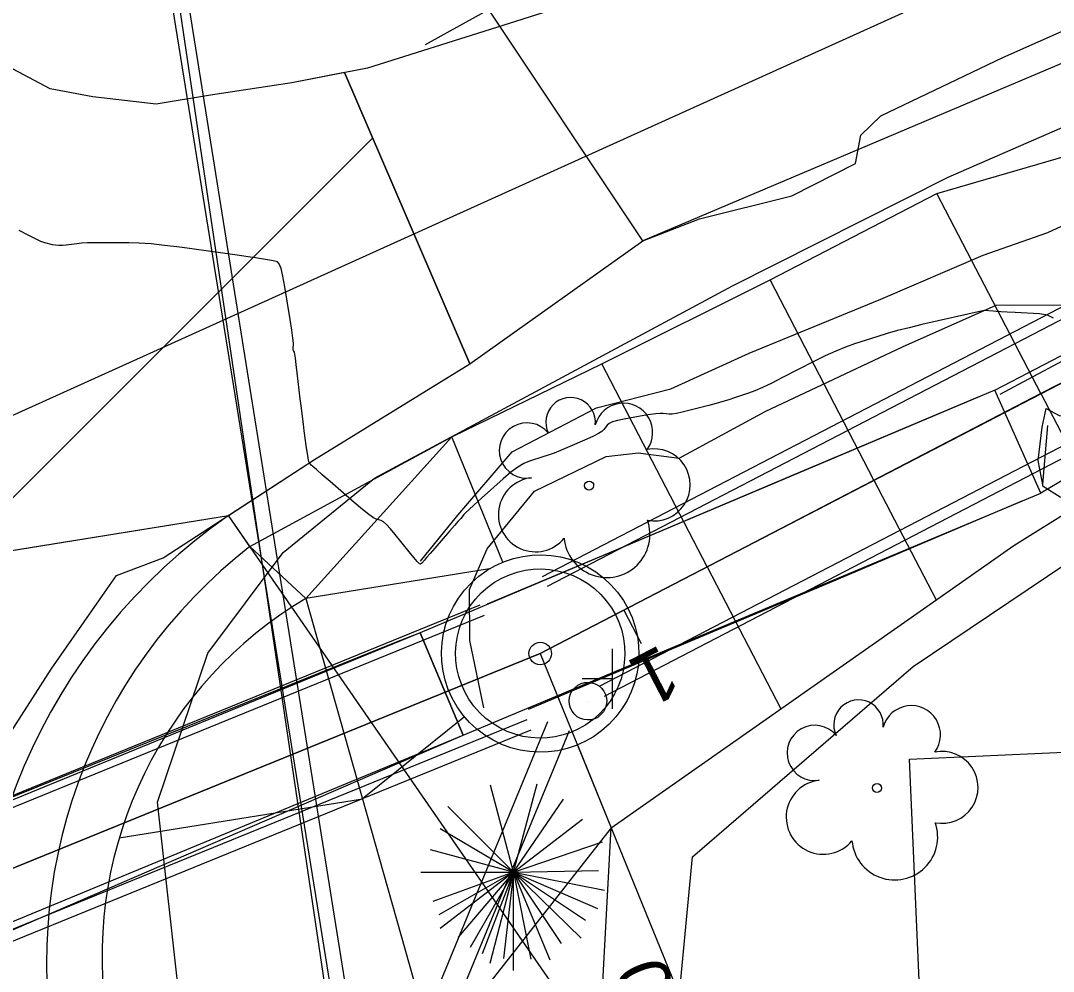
# Model space of a CAD drawing. Extents: x 2030588 to 2035216, y 462285 to 465007.
# Drawn here: x 2031264.6 to 2031319.5, y 464317.2 to 464367.7 of the extents above; entities that cross this region are included whole.
import ezdxf

# ---------------------------------------------------------------- set-up
doc = ezdxf.new("R2010")
doc.units = 0
for name, color, linetype in [('BD_X_Building', 7, 'Continuous'), ('Default', 7, 'Continuous'), ('DR_P_Cells', 7, 'Continuous'), ('DR_P_Culvert', 7, 'Continuous'), ('DR_P_Drive_Pipe', 7, 'Continuous'), ('DR_X_Culvert', 7, 'Continuous'), ('DR_X_Headwall', 7, 'Continuous'), ('DR_X_Storm_Sewer', 7, 'Continuous'), ('DT_P_Pavement_Surface', 7, 'Continuous'), ('DT_P_Slope_Break_Line', 7, 'Continuous'), ('DT_X_Contour_Major', 7, 'Continuous'), ('GE_P_Alignment', 7, 'Continuous'), ('GE_P_Alignment_100_Cardinal_Points', 7, 'Continuous'), ('GE_P_Alignment_100_Stations', 7, 'Continuous'), ('GK_Drainage_Nodes', 7, 'Continuous'), ('MD_P_CONST_LIMITS', 7, 'Continuous'), ('PV_P_EOP', 7, 'Continuous'), ('PV_P_Shoulder', 7, 'Continuous'), ('PV_X_Driveway', 7, 'Continuous'), ('PV_X_EOP', 7, 'Continuous'), ('RW_X_CL', 7, 'Continuous'), ('RW_X_Esmt_SH', 7, 'Continuous'), ('SC_Scratch1', 7, 'Continuous'), ('SN_X_Public', 7, 'Continuous'), ('SV_X_Break_Lines', 7, 'Continuous'), ('UT_X_Cable_TV', 7, 'Continuous'), ('UT_X_Electric', 7, 'Continuous'), ('UT_X_Telecom', 7, 'Continuous'), ('VG_X_Cells', 7, 'Continuous')]:
    doc.layers.add(name, color=color, linetype=linetype)

msp = doc.modelspace()

# ---------------------------------------------------------------- linework, layer by layer
at = {"layer": 'BD_X_Building'}
msp.add_lwpolyline([(2031312.882, 464304.375), (2031312.354, 464316.266), (2031311.814, 464328.452), (2031319.655, 464328.798), (2031324.902, 464329.03), (2031333.154, 464329.394), (2031342.968, 464329.827), (2031348.498, 464330.072), (2031349.056, 464317.507), (2031343.615, 464317.267), (2031344.126, 464305.755), (2031336.745, 464305.429), (2031327.934, 464305.04), (2031320.082, 464304.693)], close=True, dxfattribs=at)
at = {"layer": 'Default'}
for p, q in [((2031316.362, 464348.067), (2031316.362, 464348.067)), ((2031315.519, 464347.736), (2031315.519, 464347.736)), ((2031316.5, 464347.757), (2031316.5, 464347.757)), ((2031316.641, 464347.854), (2031316.641, 464347.854)), ((2031305.563, 464343.535), (2031305.563, 464343.535)), ((2031318.806, 464342.593), (2031318.806, 464342.593)), ((2031317.813, 464342.184), (2031317.813, 464342.184)), ((2031295.89, 464339.435), (2031295.89, 464339.435)), ((2031307.926, 464337.972), (2031307.926, 464337.972)), ((2031289.387, 464336.696), (2031289.387, 464336.696)), ((2031285.803, 464335.154), (2031285.803, 464335.154)), ((2031284.43, 464334.622), (2031284.43, 464334.622)), ((2031298.264, 464333.912), (2031298.264, 464333.912)), ((2031291.567, 464331.1), (2031291.567, 464331.1)), ((2031288.089, 464329.716), (2031288.089, 464329.716)), ((2031286.679, 464329.115), (2031286.679, 464329.115))]:
    msp.add_line(p, q, dxfattribs=at)
at = {"layer": 'DR_P_Cells'}
for centre, major_axis in [((2031292.185, 464334.061), (3.66, -3.763)), ((2031292.185, 464334.061), (3.137, -3.225)), ((2031294.719, 464331.527), (0.697, -0.717))]:
    msp.add_ellipse(centre, major_axis=major_axis, ratio=0.999989, dxfattribs=at)
at = {"layer": 'DR_P_Culvert'}
for p, q in [((2031292.309, 464338.162), (2031339.345, 464362.578)), ((2031292.578, 464337.645), (2031339.613, 464362.06)), ((2031295.342, 464332.32), (2031342.377, 464356.735)), ((2031295.611, 464331.802), (2031342.646, 464356.218)), ((2031288.982, 464336.625), (2031221.38, 464309.094)), ((2031289.202, 464336.085), (2031221.6, 464308.554)), ((2031291.465, 464330.528), (2031223.863, 464302.998)), ((2031291.685, 464329.988), (2031224.083, 464302.457))]:
    msp.add_line(p, q, dxfattribs=at)
at = {"layer": 'DR_P_Drive_Pipe'}
for p, q in [((2031285.496, 464313.266), (2031292.582, 464330.451)), ((2031287.024, 464313.693), (2031293.738, 464329.975))]:
    msp.add_line(p, q, dxfattribs=at)
at = {"layer": 'DR_X_Culvert'}
for p, q in [((2031316.362, 464348.067), (2031341.014, 464360.907)), ((2031343.516, 464357.134), (2031318.806, 464342.593)), ((2031316.362, 464348.067), (2031285.803, 464335.154)), ((2031318.806, 464342.593), (2031316.362, 464348.067)), ((2031318.806, 464342.593), (2031316.362, 464348.067)), ((2031288.089, 464329.716), (2031318.806, 464342.593)), ((2031285.803, 464335.154), (2031218.984, 464307.814)), ((2031288.089, 464329.716), (2031285.803, 464335.154)), ((2031285.803, 464335.154), (2031288.089, 464329.716)), ((2031221.368, 464302.132), (2031288.089, 464329.716))]:
    msp.add_line(p, q, dxfattribs=at)
at = {"layer": 'DR_X_Headwall'}
msp.add_line((2031318.914, 464343.074), (2031319.182, 464346.183), dxfattribs=at)
at = {"layer": 'DR_X_Storm_Sewer'}
msp.add_line((2031316.641, 464347.854), (2031341.014, 464360.907), dxfattribs=at)
for points in [[(2031289.387, 464336.696), (2031295.89, 464339.435), (2031305.563, 464343.535), (2031315.519, 464347.736)], [(2031291.567, 464331.1), (2031298.264, 464333.912), (2031307.926, 464337.972), (2031317.813, 464342.184)], [(2031285.803, 464335.154), (2031284.43, 464334.622), (2031260.346, 464324.908), (2031242.932, 464317.706), (2031218.984, 464307.814), (2031221.368, 464302.132), (2031245.351, 464311.713), (2031262.878, 464318.835), (2031286.679, 464329.115), (2031288.089, 464329.716)]]:
    msp.add_lwpolyline(points, dxfattribs=at)
at = {"layer": 'DT_P_Pavement_Surface'}
msp.add_line((2031260.803, 464339.005), (2031283.276, 464361.478), dxfattribs=at)
msp.add_lwpolyline([(2031217.338, 464453.535), (2031220.901, 464430.815), (2031223.994, 464431.313), (2031239.433, 464335.56), (2031275.613, 464341.393), (2031280.179, 464344.377), (2031288.444, 464349.459), (2031281.782, 464364.953), (2031278.976, 464364.399), (2031274.659, 464363.749), (2031271.761, 464363.269), (2031268.389, 464363.667), (2031266.116, 464364.094), (2031263.849, 464365.29), (2031262.287, 464366.863), (2031259.966, 464369.755), (2031257.582, 464371.903), (2031256.7, 464372.941), (2031246.698, 464434.974), (2031241.124, 464434.075), (2031240.612, 464437.401)], dxfattribs=at)
at = {"layer": 'DT_P_Slope_Break_Line'}
for p, q in [((2031313.281, 464358.53), (2031323.077, 464361.362)), ((2031304.406, 464353.924), (2031313.281, 464358.53)), ((2031318.809, 464347.881), (2031313.281, 464358.53)), ((2031295.458, 464349.459), (2031304.406, 464353.924)), ((2031309.934, 464343.274), (2031304.406, 464353.924)), ((2031327.683, 464352.488), (2031318.809, 464347.881)), ((2031287.49, 464345.59), (2031295.458, 464349.459)), ((2031301.06, 464338.668), (2031295.458, 464349.459)), ((2031318.809, 464347.881), (2031296.844, 464336.479)), ((2031318.809, 464347.881), (2031321.623, 464342.459)), ((2031276.75, 464339.748), (2031287.49, 464345.59)), ((2031279.724, 464336.992), (2031287.49, 464345.59)), ((2031290.205, 464338.923), (2031287.49, 464345.59)), ((2031309.934, 464343.274), (2031313.236, 464336.914)), ((2031317.366, 464339.809), (2031321.623, 464342.459)), ((2031295.957, 464324.8), (2031317.366, 464339.809)), ((2031276.75, 464339.748), (2031279.724, 464336.992)), ((2031289.491, 464338.566), (2031279.724, 464336.992)), ((2031301.06, 464338.668), (2031304.976, 464331.123)), ((2031279.724, 464336.992), (2031286.045, 464314.597)), ((2031288.159, 464330.693), (2031282.73, 464326.342)), ((2031294.165, 464329.199), (2031295.957, 464324.8)), ((2031269.802, 464324.257), (2031282.73, 464326.342)), ((2031295.957, 464324.8), (2031288.035, 464314.699)), ((2031295.379, 464314.195), (2031295.957, 464324.8))]:
    msp.add_line(p, q, dxfattribs=at)
msp.add_ellipse((2031291.052, 464317.932), major_axis=(-14.795, 16.514), ratio=0.999987, start_param=6.08887, end_param=7.247899, dxfattribs=at)
at = {"layer": 'DT_X_Contour_Major'}
msp.add_lwpolyline([(2031319.487, 464351.888), (2031319.16, 464352.052), (2031318.73, 464352.123), (2031317.445, 464352.19), (2031317.01, 464352.213), (2031316.671, 464352.232), (2031316.426, 464352.247), (2031316.277, 464352.259), (2031315.801, 464352.304), (2031312.486, 464351.548), (2031311.807, 464351.388), (2031311.189, 464351.23), (2031310.634, 464351.076), (2031310.14, 464350.924), (2031308.906, 464350.524), (2031308.423, 464350.353), (2031307.9, 464350.139), (2031307.337, 464349.883), (2031306.735, 464349.585), (2031305.073, 464348.735), (2031304.493, 464348.444), (2031303.998, 464348.208), (2031303.589, 464348.029), (2031303.265, 464347.906), (2031302.516, 464347.651), (2031302.22, 464347.555), (2031301.895, 464347.456), (2031301.541, 464347.355), (2031301.157, 464347.252), (2031300.095, 464346.975), (2031299.731, 464346.886), (2031299.435, 464346.825), (2031299.208, 464346.793), (2031299.05, 464346.791), (2031298.719, 464346.822), (2031298.562, 464346.824), (2031298.338, 464346.805), (2031298.047, 464346.767), (2031297.69, 464346.709), (2031296.648, 464346.527), (2031296.299, 464346.456), (2031296.031, 464346.38), (2031295.844, 464346.299), (2031295.739, 464346.212), (2031295.569, 464345.973), (2031295.465, 464345.874), (2031295.28, 464345.755), (2031295.015, 464345.617), (2031294.669, 464345.459), (2031293.641, 464345.013), (2031293.269, 464344.856), (2031292.927, 464344.72), (2031292.614, 464344.606), (2031292.329, 464344.513), (2031291.609, 464344.292), (2031291.319, 464344.171), (2031290.989, 464343.974), (2031290.618, 464343.7), (2031290.208, 464343.35), (2031289.06, 464342.315), (2031288.679, 464341.97), (2031288.396, 464341.71), (2031288.212, 464341.537), (2031288.126, 464341.449), (2031288.029, 464341.329), (2031287.961, 464341.248), (2031287.828, 464341.094), (2031287.63, 464340.867), (2031287.369, 464340.567), (2031286.586, 464339.67), (2031286.328, 464339.374), (2031286.141, 464339.159), (2031286.024, 464339.024), (2031285.979, 464338.969), (2031285.953, 464338.93), (2031285.941, 464338.915), (2031285.925, 464338.898), (2031285.906, 464338.881), (2031285.882, 464338.862), (2031285.815, 464338.81), (2031285.758, 464338.836), (2031285.639, 464338.954), (2031285.457, 464339.163), (2031285.212, 464339.463), (2031284.476, 464340.387), (2031284.222, 464340.693), (2031284.012, 464340.92), (2031283.847, 464341.066), (2031283.725, 464341.133), (2031283.46, 464341.204), (2031283.313, 464341.28), (2031283.07, 464341.452), (2031282.731, 464341.723), (2031282.297, 464342.09), (2031281.012, 464343.2), (2031280.588, 464343.568), (2031280.279, 464343.838), (2031280.086, 464344.01), (2031280.007, 464344.084), (2031279.911, 464344.203), (2031279.873, 464344.279), (2031279.86, 464344.335), (2031279.837, 464344.473), (2031279.805, 464344.692), (2031279.762, 464344.991), (2031279.637, 464345.898), (2031279.588, 464346.26), (2031279.537, 464346.666), (2031279.482, 464347.115), (2031279.423, 464347.607), (2031279.264, 464348.979), (2031279.209, 464349.434), (2031279.165, 464349.768), (2031279.132, 464349.983), (2031279.109, 464350.079), (2031279.061, 464350.173), (2031279.047, 464350.21), (2031279.039, 464350.248), (2031279.039, 464350.289), (2031279.045, 464350.332), (2031279.07, 464350.449), (2031279.065, 464350.568), (2031279.032, 464350.838), (2031278.97, 464351.258), (2031278.881, 464351.829), (2031278.603, 464353.551), (2031278.501, 464354.118), (2031278.403, 464354.53), (2031278.309, 464354.785), (2031278.218, 464354.885), (2031277.981, 464354.942), (2031277.889, 464354.963), (2031277.79, 464354.983), (2031277.684, 464355.002), (2031277.571, 464355.021), (2031277.26, 464355.07), (2031277.051, 464355.1), (2031276.657, 464355.156), (2031276.077, 464355.238), (2031275.312, 464355.344), (2031273.025, 464355.661), (2031272.212, 464355.765), (2031271.488, 464355.84), (2031270.853, 464355.885), (2031270.307, 464355.901), (2031268.971, 464355.905), (2031268.506, 464355.903), (2031268.114, 464355.893), (2031267.794, 464355.876), (2031267.546, 464355.851), (2031266.982, 464355.774), (2031266.778, 464355.754), (2031266.588, 464355.752), (2031266.411, 464355.767), (2031266.249, 464355.799), (2031265.835, 464355.907), (2031265.633, 464355.978), (2031265.34, 464356.11), (2031264.955, 464356.303), (2031264.478, 464356.556)], dxfattribs=at)
at = {"layer": 'GE_P_Alignment'}
for p, q in [((2031354.307, 464366.308), (2031292.185, 464334.061)), ((2031292.185, 464334.061), (2031215.324, 464302.759))]:
    msp.add_line(p, q, dxfattribs=at)
at = {"layer": 'GE_P_Alignment_100_Cardinal_Points'}
msp.add_line((2031292.185, 464334.061), (2031309.157, 464292.389), dxfattribs=at)
msp.add_ellipse((2031292.185, 464334.061), major_axis=(-0.418, 0.43), ratio=0.999989, dxfattribs=at)
at = {"layer": 'GE_P_Alignment_100_Stations'}
msp.add_line((2031296.623, 464336.364), (2031297.544, 464334.589), dxfattribs=at)
at = {"layer": 'GK_Drainage_Nodes'}
for p, q in [((2031289.004, 464337.243), (2031289.004, 464337.243)), ((2031292.185, 464334.061), (2031292.185, 464334.061)), ((2031292.185, 464334.061), (2031292.185, 464334.061)), ((2031294.719, 464331.527), (2031294.719, 464331.527)), ((2031295.367, 464330.879), (2031295.367, 464330.879))]:
    msp.add_line(p, q, dxfattribs=at)
msp.add_ellipse((2031292.185, 464334.061), major_axis=(3.137, -3.225), ratio=0.999989, dxfattribs=at)
at = {"layer": 'MD_P_CONST_LIMITS'}
for points in [[(2031335.72, 464342.732), (2031348.065, 464341.156), (2031359.796, 464346.821), (2031370.029, 464354.448), (2031376.828, 464361.456), (2031382.871, 464378.84), (2031377.102, 464386.742), (2031358.079, 464381.314), (2031336.103, 464372.313), (2031297.636, 464355.997), (2031288.946, 464369.084), (2031270.232, 464370.675), (2031259.85, 464435.069), (2031243.038, 464457.678), (2031227.121, 464556.394)], [(2031299.488, 464314.858), (2031300.288, 464323.242), (2031312.015, 464333.369), (2031323.227, 464340.901), (2031335.72, 464342.732)]]:
    msp.add_lwpolyline(points, dxfattribs=at)
at = {"layer": 'PV_P_EOP'}
for p, q in [((2031281.782, 464364.953), (2031288.444, 464349.459)), ((2031239.433, 464335.56), (2031275.613, 464341.393)), ((2031293.243, 464315.898), (2031275.613, 464341.393))]:
    msp.add_line(p, q, dxfattribs=at)
msp.add_ellipse((2031293.243, 464315.898), major_axis=(-20.684, 23.086), ratio=0.999987, start_param=6.157653, end_param=7.283599, dxfattribs=at)
at = {"layer": 'PV_P_Shoulder'}
msp.add_line((2031276.75, 464339.748), (2031275.613, 464341.393), dxfattribs=at)
msp.add_ellipse((2031293.928, 464317.64), major_axis=(-18.684, 20.851), ratio=0.999987, start_param=6.213097, end_param=7.341063, dxfattribs=at)
at = {"layer": 'PV_X_Driveway'}
msp.add_lwpolyline([(2031305.202, 464421.261), (2031303.862, 464405.212), (2031303.67, 464397.804), (2031302.921, 464389.892), (2031302.282, 464384.869), (2031300.896, 464381.621), (2031298.964, 464377.957), (2031296.445, 464373.993), (2031292.877, 464370.779), (2031289.88, 464368.535), (2031286.064, 464366.436)], dxfattribs=at)
at = {"layer": 'PV_X_EOP'}
for points in [[(2031322.372, 464378.039), (2031319.055, 464377.943), (2031312.934, 464375.745), (2031308.591, 464374.458), (2031306.493, 464372.993), (2031300.754, 464371.07), (2031295.797, 464369.242), (2031289.855, 464367.341), (2031282.993, 464365.193), (2031278.976, 464364.399), (2031274.659, 464363.749), (2031271.761, 464363.269), (2031268.389, 464363.667), (2031266.116, 464364.094), (2031263.849, 464365.29)], [(2031263.447, 464328.992), (2031266.183, 464333.232), (2031269.157, 464337.5), (2031269.657, 464338.213), (2031272.131, 464339.142), (2031280.179, 464344.377), (2031288.444, 464349.459), (2031297.636, 464355.997), (2031300.646, 464357.172), (2031305.568, 464358.396), (2031308.951, 464360.126), (2031309.243, 464361.618), (2031310.297, 464362.656), (2031316.778, 464365.748), (2031320.538, 464367.428)]]:
    msp.add_lwpolyline(points, dxfattribs=at)
at = {"layer": 'RW_X_CL'}
msp.add_line((2031247.006, 464338.982), (2031429.216, 464421.39), dxfattribs=at)
at = {"layer": 'RW_X_Esmt_SH'}
msp.add_line((2031294.07, 464235.295), (2031222.33, 464681.217), dxfattribs=at)
at = {"layer": 'SC_Scratch1'}
for p, q in [((2031292.185, 464334.061), (2031354.307, 464366.308)), ((2031250.513, 464317.09), (2031292.185, 464334.061))]:
    msp.add_line(p, q, dxfattribs=at)
at = {"layer": 'SN_X_Public'}
for p, q in [((2031296.018, 464334.315), (2031296.018, 464331.116)), ((2031296.018, 464332.716), (2031294.418, 464332.716)), ((2031296.017, 464332.716), (2031296.017, 464332.716))]:
    msp.add_line(p, q, dxfattribs=at)
at = {"layer": 'SV_X_Break_Lines'}
for points in [[(2031285.822, 464338.965), (2031287.803, 464341.415), (2031290.693, 464344.789), (2031295.184, 464347.13), (2031299.133, 464348.137), (2031303.289, 464350.026), (2031310.297, 464352.902), (2031315.739, 464355.238), (2031319.187, 464356.441), (2031323.734, 464358.552), (2031326.56, 464360.137), (2031332.567, 464362.455)], [(2031289.191, 464331.167), (2031288.444, 464334.752), (2031288.418, 464337.459), (2031289.371, 464339.62), (2031291.883, 464342.691), (2031295.683, 464344.535), (2031297.393, 464344.741), (2031299.578, 464344.446), (2031304.152, 464346.933), (2031311.457, 464350.37), (2031316.439, 464352.587), (2031320.406, 464352.606), (2031322.599, 464351.472), (2031325.288, 464348.998), (2031326.399, 464347.348), (2031327.87, 464345.917), (2031330.336, 464344.614), (2031333.038, 464343.489), (2031335.256, 464344.089), (2031337.687, 464345.643), (2031340.055, 464347.595)]]:
    msp.add_lwpolyline(points, dxfattribs=at)
msp.add_lwpolyline([(2031322.385, 464343.559), (2031321.244, 464342.355), (2031320.663, 464342.157), (2031319.834, 464342.369), (2031318.925, 464342.941), (2031318.661, 464344.333), (2031318.871, 464346.105), (2031319.086, 464347.098), (2031319.773, 464346.725), (2031321.658, 464346.402), (2031323.025, 464345.787), (2031322.825, 464344.515)], close=True, dxfattribs=at)
at = {"layer": 'UT_X_Cable_TV'}
msp.add_lwpolyline([(2031238.795, 464585.928), (2031247.129, 464533.781), (2031254.05, 464490.196), (2031262.253, 464438.839), (2031269.698, 464392.26), (2031276.53, 464349.484), (2031283.448, 464306.226), (2031289.883, 464266.155)], dxfattribs=at)
at = {"layer": 'UT_X_Electric'}
msp.add_lwpolyline([(2031221.843, 464713.466), (2031231.941, 464645.283), (2031244.284, 464562.24), (2031252.852, 464504.34), (2031260, 464456.218), (2031264.868, 464423.288), (2031269.313, 464393.306), (2031274.036, 464361.48), (2031280.969, 464314.78), (2031288.221, 464265.917), (2031292.226, 464240.822), (2031300.292, 464190.304), (2031337.855, 463955.944)], dxfattribs=at)
at = {"layer": 'UT_X_Telecom'}
msp.add_lwpolyline([(2031285.421, 464261.062), (2031282.829, 464263.075), (2031280.244, 464267.275), (2031278.637, 464271.132), (2031276.619, 464283.186), (2031273.03, 464315.325), (2031271.839, 464326.162), (2031274.513, 464334.072), (2031278.515, 464339.425), (2031283.376, 464343.379), (2031302.405, 464353.607), (2031313.884, 464359.383), (2031347.997, 464374.285), (2031378.364, 464389.658), (2031390.118, 464394.606)], dxfattribs=at)
at = {"layer": 'VG_X_Cells'}
for p, q in [((2031290.769, 464322.44), (2031289.534, 464327.053)), ((2031290.769, 464322.44), (2031292.025, 464327.138)), ((2031290.769, 464322.44), (2031293.423, 464326.325)), ((2031290.769, 464322.44), (2031287.279, 464325.927)), ((2031290.769, 464322.44), (2031294.425, 464325.245)), ((2031290.769, 464322.44), (2031286.862, 464324.737)), ((2031290.769, 464322.44), (2031295.505, 464324.047)), ((2031290.769, 464322.44), (2031286.356, 464323.624)), ((2031285.834, 464322.44), (2031290.769, 464322.44)), ((2031290.769, 464322.44), (2031286.479, 464320.879)), ((2031290.769, 464322.44), (2031286.786, 464320.159)), ((2031290.769, 464322.44), (2031286.862, 464319.446)), ((2031290.769, 464322.44), (2031287.824, 464318.974)), ((2031290.769, 464322.44), (2031288.451, 464318.426)), ((2031290.769, 464322.44), (2031289.104, 464318.101)), ((2031290.769, 464322.44), (2031289.506, 464317.584)), ((2031290.769, 464322.44), (2031290.227, 464317.849)), ((2031290.769, 464322.44), (2031295.278, 464322.532)), ((2031290.769, 464317.201), (2031290.769, 464322.44)), ((2031290.769, 464322.44), (2031291.69, 464317.804)), ((2031290.769, 464322.44), (2031292.702, 464317.772)), ((2031290.769, 464322.44), (2031293.305, 464318.647)), ((2031290.769, 464322.44), (2031294.357, 464318.919)), ((2031290.769, 464322.44), (2031294.59, 464319.886)), ((2031290.769, 464322.44), (2031295.233, 464320.499)), ((2031290.769, 464322.44), (2031295.597, 464321.482))]:
    msp.add_line(p, q, dxfattribs=at)
for centre, major_axis, start_param, end_param in [((2031293.803, 464346.358), (0.879, -0.98), 0.734954, 4.434518), ((2031296.612, 464345.82), (1.036, -1.157), 0.208904, 3.72064), ((2031291.477, 464344.855), (-0.982, 1.094), 4.662674, 8.859819), ((2031298.246, 464343.027), (1.278, -1.425), 5.362728, 8.893778), ((2031291.933, 464341.443), (-1.318, 1.469), 5.659884, 9.57643), ((2031295.732, 464340.386), (1.524, -1.7), 4.067996, 7.462828), ((2031309.108, 464330.276), (0.879, -0.98), 0.735292, 4.434856), ((2031311.918, 464329.737), (1.037, -1.156), 0.208352, 3.720087), ((2031306.783, 464328.773), (-0.982, 1.095), 4.663075, 8.86022), ((2031313.552, 464326.945), (1.279, -1.425), 5.362447, 8.893497), ((2031307.239, 464325.36), (-1.317, 1.47), 5.66036, 9.576905), ((2031311.038, 464324.304), (1.525, -1.7), 4.067719, 7.462552)]:
    msp.add_ellipse(centre, major_axis=major_axis, ratio=0.999987, start_param=start_param, end_param=end_param, dxfattribs=at)
for centre in [(2031294.786, 464342.991), (2031310.092, 464326.909)]:
    msp.add_ellipse(centre, major_axis=(-0.167, 0.172), ratio=0.999989, dxfattribs=at)

# ---------------------------------------------------------------- texts
at = {"layer": 'GE_P_Alignment_100_Cardinal_Points'}
msp.add_text('1+05.00', height=2.7997, rotation=112.1592, dxfattribs=at).set_placement((2031303.769, 464305.508))
at = {"layer": 'GE_P_Alignment_100_Stations'}
msp.add_text('1', height=2.8, rotation=207.4333, dxfattribs=at).set_placement((2031298.587, 464334.568))

doc.saveas('drawing.dxf')
